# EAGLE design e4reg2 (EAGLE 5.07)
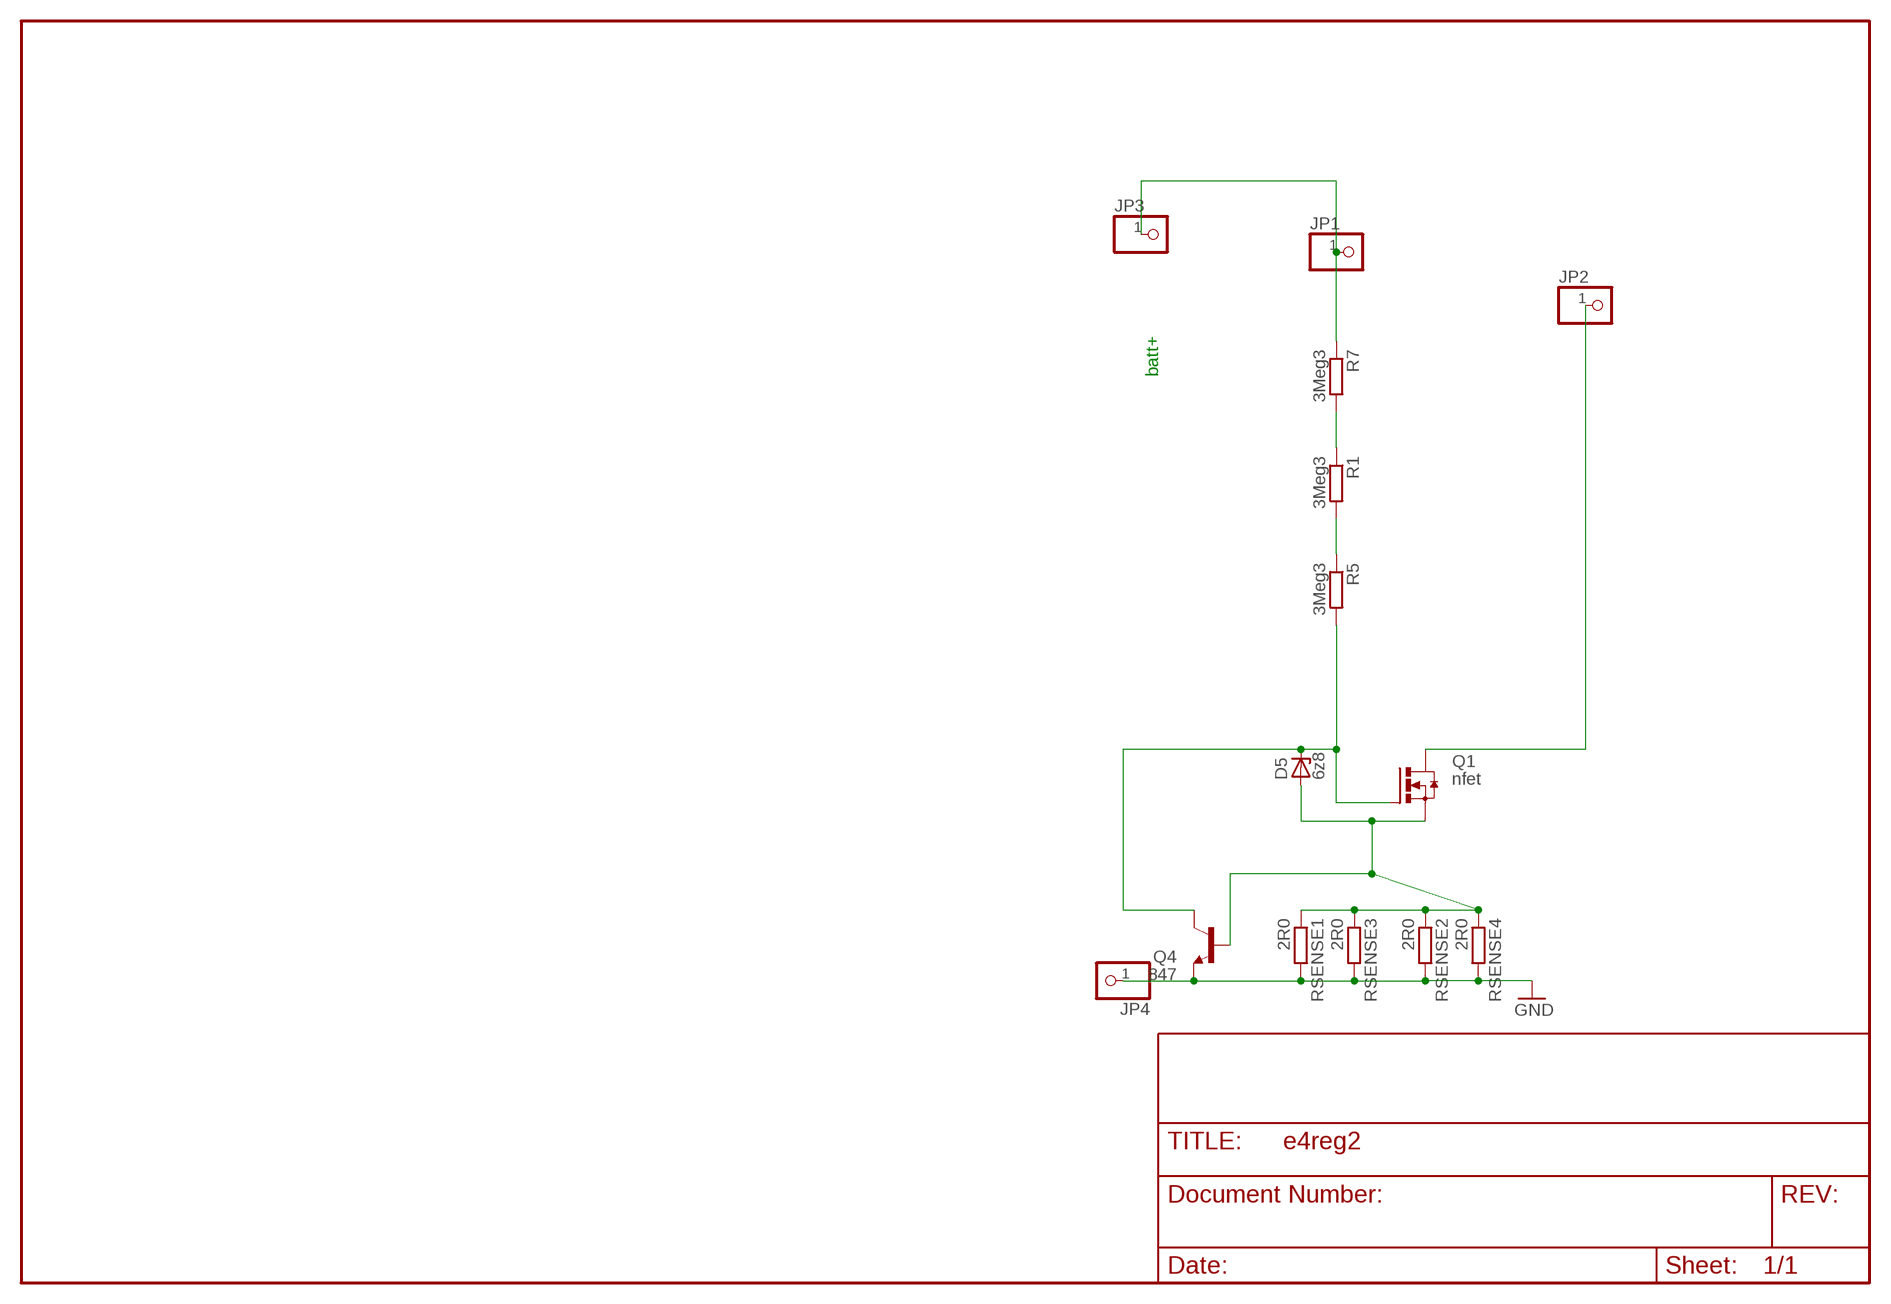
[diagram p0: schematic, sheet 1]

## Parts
D5  6z8  ZENER-DIODESOD80C  [SOD80C]
JP1  PINHD-1X11MM6  [1X1MM8]
JP2  PINHD-1X11MM6  [1X1MM8]
JP3  PINHD-1X11MM6  [1X1MM8]
JP4  PINHD-1X11MM6  [1X1MM8]
Q1  nfet  N-HEXFET_DPAK-  [TO252]
Q4  847  BC847ASMD  [SOT23]
R1  3Meg3  R-EU_R1206  [R1206]
R5  3Meg3  R-EU_R1206  [R1206]
R7  3Meg3  R-EU_R1206  [R1206]
RSENSE1  2R0  R-EU_R3216  [R3216]
RSENSE2  2R0  R-EU_R1210  [R1210]
RSENSE3  2R0  R-EU_R3216  [R3216]
RSENSE4  2R0  R-EU_R1210  [R1210]

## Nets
GND: JP4.1 Q4.2(E) RSENSE1.2 RSENSE2.2 RSENSE3.2 RSENSE4.2
LED-: JP2.1 Q1.3(D)
N$1: D5.C Q1.1(G) Q4.3(C) R5.2
N$2: R1.2 R5.1
N$4: R1.1 R7.2
S: D5.A Q1.2(S) Q4.1(B) RSENSE1.1 RSENSE2.1 RSENSE3.1 RSENSE4.1
VPLUS: JP1.1 JP3.1 R7.1

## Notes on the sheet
- batt+

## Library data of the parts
D5 = diode:ZENER-DIODE: Z-Diode
JP1-JP4 = pinhead:PINHD-1X1: PIN HEADER
Q1 = transistor-power:N-HEXFET_?-*: HEXFET® Power MOSFET
Q4 = transistor-npn:BC847*: NPN Transistor
R1 R5 R7 RSENSE1-RSENSE4 = rcl:R-EU_: RESISTOR, European symbol

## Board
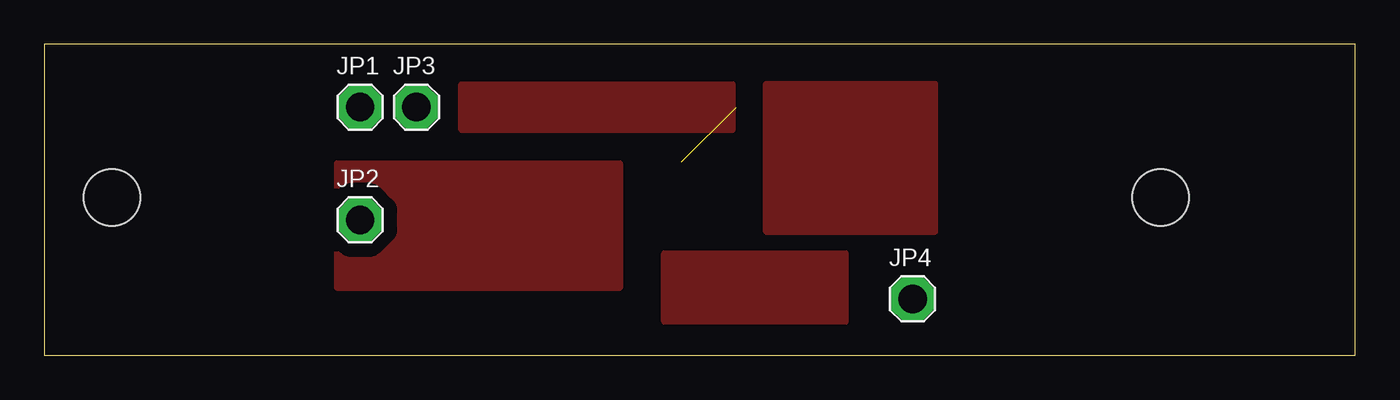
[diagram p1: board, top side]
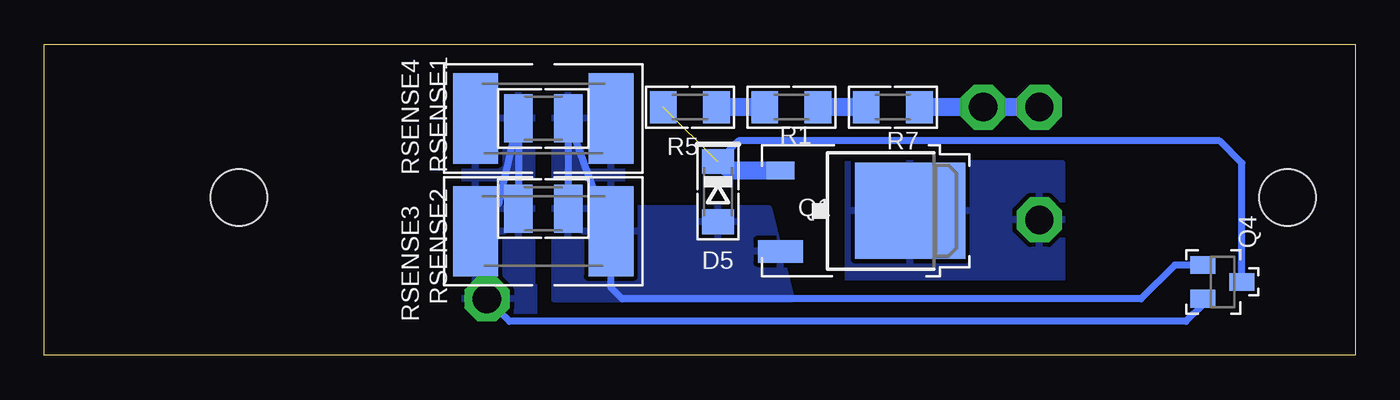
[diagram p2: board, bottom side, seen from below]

Size 73.81 x 17.5 mm. Coordinates in mm from the lower left corner, seen from the top.
Outline: 0,0 73.81,0 73.81,17.5 0,17.5 0,0
Copper layers (1*16): Top 0.035mm / dielectric 1.5mm / Bottom 0.035mm
Design rules "default *": minimum track width 10mil, minimum drill 24mil, track to track 8mil, track to pad 8mil, pad to pad 8mil, via to via 8mil, smd to smd 8mil, copper to edge 20mil, drill to drill 8mil, minimum pad ring 10mil, minimum via ring 8mil, stop-mask expansion 4mil, vias tented up to drill 0mil, thermal gap 10mil
Holes 3.2 mm at 62.87,8.89 3.81,8.89

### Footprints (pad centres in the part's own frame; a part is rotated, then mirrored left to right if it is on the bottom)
SOD80C = smd 1.4 x 1.8: A 1.7,0; C -1.7,0
1X1MM8 = drill 1.6 pad 2.54 octagon: 1 0,0
TO252 = smd 1 x 1.6: 1 -2.28,-3.53 | smd 1.27 x 2.54: 2 2.28,-3.53 | smd 5.4 x 6.2: 3 0,3.77
SOT23 = smd 1 x 1.4: 1 -0.95,-1.1; 2 0.95,-1.1; 3 0,1.1
R1206 = smd 1.5 x 1.8: 1 -1.5,0; 2 1.5,0
R3216 = smd 2.54 x 5.08: 1 -3.81,0; 2 3.81,0
R1210 = smd 1.6 x 2.7: 1 -1.4,0; 2 1.4,0

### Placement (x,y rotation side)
D5  35.88,9.21 270 bottom
JP1  17.78,13.97 0 top
JP2  17.78,7.62 0 top
JP3  20.95,13.97 0 top
JP4  48.9,3.17 0 top
Q1  28.83,8.13 270 bottom
Q4  7.47,4.13 270 bottom
R1  31.75,13.97 180 bottom
R5  37.47,13.97 180 bottom
R7  26.04,13.97 180 bottom
RSENSE1  45.72,13.34 180 bottom
RSENSE2  45.72,8.26 180 bottom
RSENSE3  45.72,6.99 180 bottom
RSENSE4  45.72,13.34 180 bottom

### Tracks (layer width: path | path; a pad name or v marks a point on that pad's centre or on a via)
GND
  Bottom 0.406: RSENSE2.2 RSENSE4.2 48.2,8.57 RSENSE3.2 48.52,3.55 JP4.1 48.26,2.54 47.62,1.91 9.53,1.91 8.57,2.86 Q4.2
  pour Bottom (isolate 0.813, rank 2): 46.35,14.61 50.16,14.61 50.16,2.54 43.81,2.54 43.81,3.81 46.35,3.81
LED-
  pour Bottom (isolate 0.813, rank 2): 16.51,10.79 28.57,10.79 28.57,3.81 16.51,3.81
N$1  (1 unrouted)
  Bottom 0.406: Q4.3 6.37,10.82 7.62,12.06 34.72,12.06 D5.C
  Bottom 1.016: Q1.1 35.11,10.41 D5.C
N$2
  Bottom 1.016: R1.2 R5.1
N$3
  pour Top (isolate 0.813, rank 2): 34.92,5.71 45.09,5.71 45.09,1.91 34.92,1.91
N$4
  Bottom 1.016: R7.2 R1.1
N$5
  pour Top (isolate 0.813, rank 2): 40.64,15.24 40.64,6.99 50.16,6.99 50.16,15.24
N$6
  pour Top (isolate 0.813, rank 2): 16.51,10.79 32.38,10.79 32.38,3.81 16.51,3.81
N$8
  pour Top (isolate 0.813, rank 2): 23.5,15.24 38.73,15.24 38.73,12.7 23.5,12.7
S
  Bottom 0.406: Q1.2 32.89,5.85 | RSENSE3.1 42.6,8.57 RSENSE4.1 RSENSE2.1 | Q4.1 10.16,5.08 12.06,3.17 41.27,3.17 41.91,3.81 RSENSE3.1 | RSENSE3.1 41.91,7.25
  pour Bottom (isolate 0.61): 33.02,8.26 41.27,8.26 41.27,14.61 45.09,14.61 45.09,3.17 31.75,3.17
VPLUS
  Bottom 1.016: R7.1 JP3.1 JP1.1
